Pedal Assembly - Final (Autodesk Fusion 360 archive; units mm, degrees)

design "Pedal Assembly" references "Large Bearing", "Pedal Cap", "Cheese Head Screw ISO 7048 - M3 x 20 - H Steel 4.6 Plain", "O-ring", "Hexagon Thin Nut ISO 4035 - M3 Steel 6 Plain", "Spindle", "Hex Nut", "Small Bearing", "Pedal"
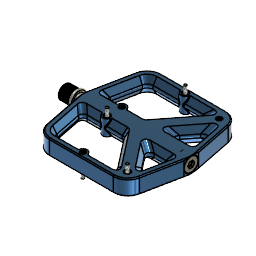
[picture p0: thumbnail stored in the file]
part number: 2025-12-16-16-23-51-010
component_insert "Component Insert1"
component_insert "Component Insert2"
component_insert "Component Insert3"
component_insert "Component Insert4"
component_insert "Component Insert5"
component_insert "Component Insert6"
component_insert "Component Insert7"
step "GeometricRelationship1" Offset 0 Offset 0
step "GeometricRelationship2" Offset 0 Offset 0
step "GeometricRelationship3" Offset 0 Offset 0
step "GeometricRelationship4" Offset 0
joint "Assemble1" alignAngle 0 alignOffsetX 0 alignOffsetY 0 alignOffsetZ 0
joint "Assemble2" alignAngle 0 alignOffsetX 0 alignOffsetY 0 alignOffsetZ 0
step "Screw1"
joint "Assemble3" alignAngle 0 alignOffsetX 0 alignOffsetY 0 alignOffsetZ 0
step "Screw2"
joint "Assemble4" alignAngle 0 alignOffsetX 20.135 alignOffsetY -60 alignOffsetZ 0
joint "Assemble5" alignAngle 0 alignOffsetX 0 alignOffsetY 0 alignOffsetZ -5
step "Screw3"
joint "Assemble6" alignAngle 0 alignOffsetX -40.152 alignOffsetY -99.505 alignOffsetZ 0
joint "Assemble7" alignAngle 0 alignOffsetX 0 alignOffsetY 0 alignOffsetZ -5
step "Screw4"
joint "Assemble8" alignAngle 0 alignOffsetX 0 alignOffsetY 0 alignOffsetZ 0
step "Screw5"
joint "Assemble9" alignAngle 0 alignOffsetX 20.135 alignOffsetY -60 alignOffsetZ 0
joint "Assemble10" alignAngle 0 alignOffsetX 0 alignOffsetY 0 alignOffsetZ 5
step "Screw6"
joint "Assemble11" alignAngle 0 alignOffsetX -40.152 alignOffsetY -99.505 alignOffsetZ 0
joint "Assemble12" alignAngle 0 alignOffsetX 0 alignOffsetY 0 alignOffsetZ 5
step "Nut7"
joint "Assemble13" alignAngle 0 alignOffsetX 40.152 alignOffsetY -99.505 alignOffsetZ 0
joint "Assemble14" alignAngle 0 alignOffsetX 0 alignOffsetY 0 alignOffsetZ -0.432
step "Nut8"
joint "Assemble15" alignAngle 0 alignOffsetX 60.288 alignOffsetY -39.505 alignOffsetZ 0
joint "Assemble16" alignAngle 0 alignOffsetX 0 alignOffsetY 0 alignOffsetZ -0.432
step "Nut9"
joint "Assemble17" alignAngle 0 alignOffsetX 0 alignOffsetY 0 alignOffsetZ 0
joint "Assemble18" alignAngle 0 alignOffsetX 0 alignOffsetY 0 alignOffsetZ -0.432
step "Nut10"
joint "Assemble19" alignAngle 0 alignOffsetX 40.152 alignOffsetY -99.505 alignOffsetZ 0
joint "Assemble20" alignAngle 0 alignOffsetX 0 alignOffsetY 0 alignOffsetZ -0.432
step "Nut11"
joint "Assemble21" alignAngle 0 alignOffsetX 60.288 alignOffsetY -39.505 alignOffsetZ 0
joint "Assemble22" alignAngle 0 alignOffsetX 0 alignOffsetY 0 alignOffsetZ -0.432
step "Nut12"
joint "Assemble23" alignAngle 0 alignOffsetX 0 alignOffsetY 0 alignOffsetZ 0
joint "Assemble24" alignAngle 0 alignOffsetX 0 alignOffsetY 0 alignOffsetZ -0.432

design "Pedal"
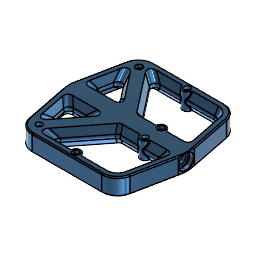
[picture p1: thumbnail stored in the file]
part number: 2025-12-16-15-12-29-748
sketch "Sketch1" plane through (0, 0, 0) normal (0, 0, 1) x axis (1, 0, 0)
  line L1 (55, -7.5) -> (-55, -7.5)
  line L2 (55, 7.5) -> (55, -7.5)
  line L3 (-55, 7.5) -> (55, 7.5)
  line L4 (-55, -7.5) -> (-55, 7.5)
  line L5 (55, 7.5) -> (-55, -7.5)
  line L6 (-55, 7.5) -> (55, -7.5)
  line L7 (55, 0) -> (-55, 0)
  line L8 (45, 57.5) -> (-45, 57.5)
  line L9 (-45, 57.5) -> (-55, 7.5)
  line L10 (55, 7.5) -> (45, 57.5)
  line L11 (-45, -57.5) -> (-55, -7.5)
  line L12 (45, -57.5) -> (-45, -57.5)
  line L13 (55, -7.5) -> (45, -57.5)
  point P6 (0, 0)
  point P1 (0, 0)
  point P7 (-55, 0)
  point P8 (55, 0)
  point P4 (55, 7.5)
  point P14 (55, -7.5)
  point P5 (-55, 7.5)
  point P11 (-55, -7.5)
  point P9 (-45, 57.5)
  point P12 (-45, -57.5)
  point P10 (45, 57.5)
  point P13 (45, -57.5)
  point P3 (55, -7.5)
  horizontal L1
  perpendicular L1 L2
  parallel L1 L3
  parallel L2 L4
  coincident L5 P6
  coincident L6 P6
  coincident P1 P6
  midpoint L4 P7
  midpoint L2 P8
  horizontal L8
  equal L9 L10
  symmetric P4 L7 P14
  symmetric P5 L7 P11
  symmetric L7 P9 P12
  symmetric L7 P10 P13
  dimension "d1" distance P4 P5 = 110
  dimension "d2" distance P3 P4 = 15
  dimension "d3" distance L7 L8 = 57.5
  dimension "d4" distance P9 P10 = 90
extrude "Extrude1" new body sketch "Sketch1" profile of L2 L4 L8 L9 L10 L11 L12 L13 distance 16
fillet "Fillet1" radius 15
sketch "Sketch2" plane through (0, 0, 8) normal (0, 0, 1) x axis (-1, 0, 0)
  line L1 (-55, 7.5) -> (-47.4117, 45.4417)
  line L2 (-55, -7.5) -> (-55, 7.5)
  line L3 (-47.4117, -45.4417) -> (-55, -7.5)
  line L4 (32.7029, -57.5) -> (-32.7029, -57.5)
  line L5 (55, -7.5) -> (47.4117, -45.4417)
  line L6 (55, 7.5) -> (55, -7.5)
  line L7 (47.4117, 45.4417) -> (55, 7.5)
  line L8 (-32.7029, 57.5) -> (32.7029, 57.5)
  line L9 (-55, -7.5) -> (55, -7.5)
  line L10 (-55, 7.5) -> (55, 7.5)
  line L11 (42.2128, -54.1001) -> (0, 0)
  line L12 (42.2128, 54.1001) -> (0, 0)
  line L13 (45.5479, 50.2465) -> (6.342, 0)
  line L14 (45.5479, -50.2465) -> (6.342, 0)
  line L15 (37.8212, 56.5998) -> (-6.342, 0)
  line L16 (37.8212, -56.5998) -> (-6.342, 0)
  line L17 (50, -7.0049) -> (42.5087, -44.4612)
  line L18 (50, 7.0049) -> (50, -7.0049)
  line L19 (42.5087, 44.4612) -> (50, 7.0049)
  line L20 (-32.7029, 52.5) -> (32.7029, 52.5)
  line L21 (-50, 7.0049) -> (-42.5087, 44.4612)
  line L22 (-50, -7.0049) -> (-50, 7.0049)
  line L23 (-42.5087, -44.4612) -> (-50, -7.0049)
  line L24 (32.7029, -52.5) -> (-32.7029, -52.5)
  arc A1 centre (-32.7029, 42.5) radius 15 clockwise from (-47.4117, 45.4417) to (-32.7029, 57.5)
  arc A2 centre (-32.7029, -42.5) radius 15 clockwise from (-32.7029, -57.5) to (-47.4117, -45.4417)
  arc A3 centre (32.7029, -42.5) radius 15 clockwise from (47.4117, -45.4417) to (32.7029, -57.5)
  arc A4 centre (32.7029, 42.5) radius 15 clockwise from (32.7029, 57.5) to (47.4117, 45.4417)
  arc A5 centre (32.7029, -42.5) radius 10 clockwise from (42.5087, -44.4612) to (32.7029, -52.5)
  arc A6 centre (32.7029, 42.5) radius 10 clockwise from (32.7029, 52.5) to (42.5087, 44.4612)
  arc A7 centre (-32.7029, 42.5) radius 10 clockwise from (-42.5087, 44.4612) to (-32.7029, 52.5)
  arc A8 centre (-32.7029, -42.5) radius 10 clockwise from (-32.7029, -52.5) to (-42.5087, -44.4612)
  point P13 (55, -7.5)
  point P18 (55, -7.5)
  point P6 (-55, -7.5)
  point P19 (-55, -7.5)
  point P14 (55, 7.5)
  point P20 (55, 7.5)
  point P5 (-55, 7.5)
  point P21 (-55, 7.5)
  point P1 (0, 0)
  point P22 (0, 0)
  point P23 (42.2128, -54.1001)
  point P24 (0, 0)
  point P25 (42.2128, 54.1001)
  point P31 (37.8212, -56.5998)
  point P28 (45.5479, -50.2465)
  point P27 (45.5479, 50.2465)
  point P30 (37.8212, 56.5998)
  coincident P13 P18
  coincident P6 P19
  coincident P14 P20
  coincident P5 P21
  coincident P1 P22
  midpoint A3 P23
  coincident P1 P24
  midpoint A4 P25
  coincident A3 P31
  coincident A3 P28
  coincident A4 P27
  coincident A4 P30
  dimension "d9" = 5
  dimension "d10" = -5 (= "-d9")
  dimension "d11" = -5
extrude "Extrude2" cut sketch "Sketch2" profile of L9 L10 L13 L14 L15 L16 A6 A5 L17 L19 L20 A7 L21 L23 A8 L24 against normal blind 8 taper -30
fillet "Fillet2" radius 5
mirror "Mirror1" mirrorStitchTolerance 0.1
fillet "Fillet3" ChordLen 3.5
sketch "Sketch3" plane through (0, 0, 0) normal (0, 0, 1) x axis (1, 0, 0)
  line L1 (55, -7.5) -> (55, 7.5)
  line L2 (55, 7.5) -> (55, -7.5)
  line L3 (-55, 7.5) -> (-55, -7.5)
  line L4 (-55, 0) -> (55, 0)
  line L5 (51, 7) -> (55, 7)
  line L6 (51, 4.5) -> (51, 7)
  line L7 (-42.5, 4.5) -> (51, 4.5)
  line L8 (-42.5, 5) -> (-42.5, 4.5)
  line L9 (-45, 5) -> (-42.5, 5)
  line L10 (-45, 7) -> (-45, 5)
  line L11 (-55, 7) -> (-45, 7)
  point P6 (55, 0)
  point P7 (-55, 0)
  point P8 (55, 7)
  point P15 (-55, 7)
  point P9 (51, 7)
  point P10 (51, 4.5)
  point P11 (-42.5, 4.5)
  point P12 (-42.5, 5)
  midpoint L2 P6
  midpoint L3 P7
  coincident L1 P8
  perpendicular L1 L5
  perpendicular L5 L6
  perpendicular L6 L7
  perpendicular L7 L8
  perpendicular L3 L9
  perpendicular L9 L10
  coincident L3 P15
  perpendicular L3 L11
  dimension "d20" = 14
  dimension "d21" distance P8 P9 = 4
  dimension "d22" = 9
  dimension "d23" distance P10 P11 = 93.5
  dimension "d24" = 10
  dimension "d25" distance P12 L10 = 2.5
  dimension "d26" = 14
revolve "Revolve1" sketch "Sketch3" AlongAngle 360
sketch "Screw Loc" plane through (0, 0, 8) normal (0, 0, 1) x axis (-1, 0, 0)
  line L1 (44.0595, -36.7075) -> (48.8651, -12.6793)
  line L2 (17.6511, -14.4939) -> (36.3996, -38.522)
  line L3 (44.6191, -7.5) -> (21.065, -7.5)
  line L4 (-48.8651, -12.6793) -> (-42.5087, -44.4612)
  line L5 (-2.6036, -7.5) -> (-44.6191, -7.5)
  line L6 (29.1652, -45.5061) -> (0.8103, -9.1664)
  line L7 (-32.7029, -52.5) -> (25.7513, -52.5)
  line L8 (48.8651, 12.6793) -> (44.0595, 36.7075)
  line L9 (21.065, 7.5) -> (44.6191, 7.5)
  line L10 (36.3996, 38.522) -> (17.6511, 14.4939)
  line L11 (0.8103, 9.1664) -> (29.1652, 45.5061)
  line L12 (-44.6191, 7.5) -> (-2.6036, 7.5)
  line L13 (-42.5087, 44.4612) -> (-48.8651, 12.6793)
  line L14 (25.7513, 52.5) -> (-32.7029, 52.5)
  line L15 (-55, 7.5) -> (-47.4117, 45.4417)
  line L16 (-55, -7.5) -> (-55, 7.5)
  line L17 (-47.4117, -45.4417) -> (-55, -7.5)
  line L18 (32.7029, -57.5) -> (-32.7029, -57.5)
  line L19 (55, -7.5) -> (47.4117, -45.4417)
  line L20 (55, 7.5) -> (55, -7.5)
  line L21 (47.4117, 45.4417) -> (55, 7.5)
  line L22 (-32.7029, 57.5) -> (32.7029, 57.5)
  line L23 (42.2128, -54.1001) -> (0, 0)
  line L24 (55, 0) -> (0, 0)
  closed curve K1 centre (39.0153, -32.4891)
  closed curve K2 centre (24.022, -13.2735)
  closed curve K3 centre (42.8584, -13.2735)
  closed curve K4 centre (-42.8584, -13.2735)
  closed curve K5 centre (-3.3081, -13.2735)
  closed curve K6 centre (22.7943, -46.7265)
  arc A1 centre (-32.7029, -42.5) radius 10 clockwise from (-32.7029, -52.5) to (-42.5087, -44.4612)
  closed curve K7 centre (42.8584, 13.2735)
  closed curve K8 centre (24.022, 13.2735)
  closed curve K9 centre (39.0153, 32.4891)
  closed curve K10 centre (22.7943, 46.7265)
  closed curve K11 centre (-3.3081, 13.2735)
  closed curve K12 centre (-42.8584, 13.2735)
  arc A2 centre (-32.7029, 42.5) radius 10 clockwise from (-42.5087, 44.4612) to (-32.7029, 52.5)
  arc A3 centre (-32.7029, 42.5) radius 15 clockwise from (-47.4117, 45.4417) to (-32.7029, 57.5)
  arc A4 centre (-32.7029, -42.5) radius 15 clockwise from (-32.7029, -57.5) to (-47.4117, -45.4417)
  arc A5 centre (32.7029, -42.5) radius 15 clockwise from (47.4117, -45.4417) to (32.7029, -57.5)
  arc A6 centre (32.7029, 42.5) radius 15 clockwise from (32.7029, 57.5) to (47.4117, 45.4417)
  circle C1 centre (-3.4758, -52.5) radius 4.5
  circle C2 centre (36.6763, -47.0045) radius 4.5
  circle C3 centre (-23.6113, -7.5) radius 4.5
  circle C4 centre (-23.6113, -7.5) radius 2.75
  circle C5 centre (-3.4758, -52.5) radius 2.75
  circle C6 centre (36.6763, -47.0045) radius 2.75
  circle C7 centre (36.6763, 47.0045) radius 4.5
  circle C8 centre (36.6763, 47.0045) radius 2.75
  circle C9 centre (-3.4758, 52.5) radius 4.5
  circle C10 centre (-3.4758, 52.5) radius 2.75
  circle C11 centre (-23.6113, 7.5) radius 4.5
  circle C12 centre (-23.6113, 7.5) radius 2.75
  point P58 (-3.4758, -52.5)
  point P61 (36.6763, -47.0045)
  point P59 (0, 0)
  point P62 (0, 0)
  point P63 (55, 0)
  point P64 (-23.6113, -7.5)
  point P60 (42.2128, -54.1001)
  midpoint L7 P58
  coincident L23 P61
  coincident P59 P62
  midpoint L20 P63
  coincident L5 P64
  midpoint L5 P64
  equal C1 C3
  concentric C3 C4
  concentric C1 C5
  concentric C2 C6
  equal C5 C6
  equal C4 C5
  symmetric C1 L24 C9
  symmetric C2 L24 C7
  symmetric L24 C3 C11
  symmetric L24 C4 C12
  symmetric L24 C5 C10
  symmetric L24 C6 C8
  dimension "d28" diameter C1 = 9
  dimension "d29" diameter C2 = 9
  dimension "d30" distance P60 P61 = 9
  dimension "d31" diameter C4 = 5.5
extrude "Extrude3" add sketch "Screw Loc" profile of L5 L7 L12 L14 C1 C3 C4 C5 C9 C10 C11 C12 to an object
extrude "Extrude4" cut sketch "Screw Loc" profile of L7 L12 C5 C8 C12 against normal blind 3
extrude "Extrude5" sketch "Screw Loc" profile of L5 L14 C4 C6 C10 blind 3
sketch "Sketch5" plane through (0, 0, 8) normal (0, 0, 1) x axis (-1, 0, 0)
  line L1 (44.0595, -36.7075) -> (48.8651, -12.6793)
  line L2 (17.6511, -14.4939) -> (36.3996, -38.522)
  line L3 (44.6191, -7.5) -> (21.065, -7.5)
  line L4 (-48.8651, -12.6793) -> (-42.5087, -44.4612)
  line L5 (-28.1113, -7.5) -> (-44.6191, -7.5)
  line L6 (-2.6036, -7.5) -> (-19.1113, -7.5)
  line L7 (29.1652, -45.5061) -> (0.8103, -9.1664)
  line L8 (1.0242, -52.5) -> (25.7513, -52.5)
  line L9 (-32.7029, -52.5) -> (-7.9758, -52.5)
  line L10 (48.8651, 12.6793) -> (44.0595, 36.7075)
  line L11 (21.065, 7.5) -> (44.6191, 7.5)
  line L12 (36.3996, 38.522) -> (17.6511, 14.4939)
  line L13 (0.8103, 9.1664) -> (29.1652, 45.5061)
  line L14 (-19.1113, 7.5) -> (-2.6036, 7.5)
  line L15 (-44.6191, 7.5) -> (-28.1113, 7.5)
  line L16 (-42.5087, 44.4612) -> (-48.8651, 12.6793)
  line L17 (-7.9758, 52.5) -> (-32.7029, 52.5)
  line L18 (25.7513, 52.5) -> (1.0242, 52.5)
  line L19 (-55, 7.5) -> (-47.4117, 45.4417)
  line L20 (-55, -7.5) -> (-55, 7.5)
  line L21 (-47.4117, -45.4417) -> (-55, -7.5)
  line L22 (32.7029, -57.5) -> (-32.7029, -57.5)
  line L23 (55, -7.5) -> (47.4117, -45.4417)
  line L24 (55, 7.5) -> (55, -7.5)
  line L25 (47.4117, 45.4417) -> (55, 7.5)
  line L26 (-32.7029, 57.5) -> (32.7029, 57.5)
  line L27 (-0.6008, -54.1599) -> (-3.4758, -55.8198)
  line L28 (-0.6008, -50.8401) -> (-0.6008, -54.1599)
  line L29 (-3.4758, -49.1802) -> (-0.6008, -50.8401)
  line L30 (-6.3508, -50.8401) -> (-3.4758, -49.1802)
  line L31 (-6.3508, -54.1599) -> (-6.3508, -50.8401)
  line L32 (-3.4758, -55.8198) -> (-6.3508, -54.1599)
  line L33 (39.5513, -48.6644) -> (36.6763, -50.3243)
  line L34 (39.5513, -45.3447) -> (39.5513, -48.6644)
  line L35 (36.6763, -43.6848) -> (39.5513, -45.3447)
  line L36 (33.8013, -45.3447) -> (36.6763, -43.6848)
  line L37 (33.8013, -48.6644) -> (33.8013, -45.3447)
  line L38 (36.6763, -50.3243) -> (33.8013, -48.6644)
  line L39 (-23.6113, -10.8198) -> (-26.4863, -9.1599)
  line L40 (-20.7363, -9.1599) -> (-23.6113, -10.8198)
  line L41 (-20.7363, -5.8401) -> (-20.7363, -9.1599)
  line L42 (-23.6113, -4.1802) -> (-20.7363, -5.8401)
  line L43 (-26.4863, -5.8401) -> (-23.6113, -4.1802)
  line L44 (-26.4863, -9.1599) -> (-26.4863, -5.8401)
  line L45 (-20.7363, 5.8401) -> (-23.6113, 4.1802)
  line L46 (-20.7363, 9.1599) -> (-20.7363, 5.8401)
  line L47 (-23.6113, 10.8198) -> (-20.7363, 9.1599)
  line L48 (-26.4863, 9.1599) -> (-23.6113, 10.8198)
  line L49 (-26.4863, 5.8401) -> (-26.4863, 9.1599)
  line L50 (-23.6113, 4.1802) -> (-26.4863, 5.8401)
  line L51 (-0.6008, 50.8401) -> (-3.4758, 49.1802)
  line L52 (-0.6008, 54.1599) -> (-0.6008, 50.8401)
  line L53 (-3.4758, 55.8198) -> (-0.6008, 54.1599)
  line L54 (-6.3508, 54.1599) -> (-3.4758, 55.8198)
  line L55 (-6.3508, 50.8401) -> (-6.3508, 54.1599)
  line L56 (-3.4758, 49.1802) -> (-6.3508, 50.8401)
  line L57 (39.5513, 45.3447) -> (36.6763, 43.6848)
  line L58 (39.5513, 48.6644) -> (39.5513, 45.3447)
  line L59 (36.6763, 50.3243) -> (39.5513, 48.6644)
  line L60 (33.8013, 48.6644) -> (36.6763, 50.3243)
  line L61 (33.8013, 45.3447) -> (33.8013, 48.6644)
  line L62 (36.6763, 43.6848) -> (33.8013, 45.3447)
  circle C1 centre (36.6763, 47.0045) radius 2.75
  circle C2 centre (-23.6113, 7.5) radius 2.75
  circle C3 centre (-3.4758, -52.5) radius 2.75
  closed curve K1 centre (39.0153, -32.4891)
  closed curve K2 centre (24.022, -13.2735)
  closed curve K3 centre (42.8584, -13.2735)
  closed curve K4 centre (-42.8584, -13.2735)
  arc A1 centre (-23.6113, -7.5) radius 4.5 clockwise from (-19.1113, -7.5) to (-28.1113, -7.5)
  closed curve K5 centre (-3.3081, -13.2735)
  closed curve K6 centre (22.7943, -46.7265)
  arc A2 centre (-3.4758, -52.5) radius 4.5 clockwise from (-7.9758, -52.5) to (1.0242, -52.5)
  arc A3 centre (-32.7029, -42.5) radius 10 clockwise from (-32.7029, -52.5) to (-42.5087, -44.4612)
  closed curve K7 centre (42.8584, 13.2735)
  closed curve K8 centre (24.022, 13.2735)
  closed curve K9 centre (39.0153, 32.4891)
  closed curve K10 centre (22.7943, 46.7265)
  closed curve K11 centre (-3.3081, 13.2735)
  arc A4 centre (-23.6113, 7.5) radius 4.5 clockwise from (-28.1113, 7.5) to (-19.1113, 7.5)
  closed curve K12 centre (-42.8584, 13.2735)
  arc A5 centre (-32.7029, 42.5) radius 10 clockwise from (-42.5087, 44.4612) to (-32.7029, 52.5)
  arc A6 centre (-3.4758, 52.5) radius 4.5 clockwise from (1.0242, 52.5) to (-7.9758, 52.5)
  arc A7 centre (-32.7029, 42.5) radius 15 clockwise from (-47.4117, 45.4417) to (-32.7029, 57.5)
  arc A8 centre (-32.7029, -42.5) radius 15 clockwise from (-32.7029, -57.5) to (-47.4117, -45.4417)
  arc A9 centre (32.7029, -42.5) radius 15 clockwise from (47.4117, -45.4417) to (32.7029, -57.5)
  arc A10 centre (32.7029, 42.5) radius 15 clockwise from (32.7029, 57.5) to (47.4117, 45.4417)
  point P72 (-3.4758, -52.5)
  point P83 (-3.4758, -52.5)
  point P71 (36.6763, -47.0045)
  point P90 (36.6763, -47.0045)
  point P20 (-23.6113, -7.5)
  point P97 (-23.6113, -7.5)
  point P3 (-23.6113, 7.5)
  point P104 (-23.6113, 7.5)
  point P75 (-3.4758, 52.5)
  point P111 (-3.4758, 52.5)
  point P76 (36.6763, 47.0045)
  point P118 (36.6763, 47.0045)
  coincident P72 P83
  vertical L28
  coincident P71 P90
  coincident P20 P97
  coincident P3 P104
  coincident P75 P111
  coincident P76 P118
  vertical L61
  vertical L52
  vertical L46
  vertical L44
  vertical L37
  equal L31 L37
  equal L31 L44
  equal L44 L49
  equal L49 L55
  equal L55 L61
  dimension "d39" distance L28 L31 = 5.75
extrude "Extrude6" cut sketch "Sketch5" profile of L33 L34 L35 L36 L37 L38 L39 L40 L41 L42 L43 L44 L51 L52 L53 L54 L55 L56 against normal blind 3
extrude "Extrude7" sketch "Sketch5" profile of C1 C2 C3 L27 L28 L29 L30 L31 L32 L45 L46 L47 L48 L49 L50 L57 L58 L59 L60 L61 L62 blind 3
hole "Hole1" HoleDiameter 3 TipAngle 180
fillet "Fillet4" ChordLen 1
chamfer "Chamfer1" distance 1
chamfer "Chamfer2" distance 0.25
thread "Thread1" ThreadOffset 0 ThreadLength 10
chamfer "Chamfer3" distance 0.25
chamfer "Chamfer4" distance 1

design "Pedal Cap"
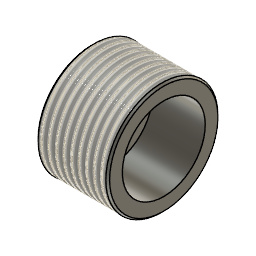
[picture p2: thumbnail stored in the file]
part number: 2025-12-16-11-19-28-387
sketch "Sketch1" plane through (0, 0, 0) normal (0, 0, 1) x axis (1, 0, 0)
  line L1 (7, 0) -> (0, 0)
  line L2 (0, 5.5) -> (0, 0)
  line L3 (7, 5.5) -> (0, 5.5)
  line L4 (7, 7.5) -> (7, 5.5)
  line L5 (-2.5, 7.5) -> (7, 7.5)
  line L6 (-2.5, 0) -> (-2.5, 7.5)
  line L7 (0, 0) -> (-2.5, 0)
  point P1 (0, 0)
  point P2 (0, 0)
  point P4 (0, 0)
  point P10 (0, 0)
  point P3 (7, 0)
  point P9 (-2.5, 0)
  point P5 (0, 5.5)
  point P6 (7, 5.5)
  coincident P1 P2
  horizontal L1
  coincident P1 P4
  perpendicular L1 L2
  perpendicular L2 L3
  perpendicular L3 L4
  perpendicular L4 L5
  perpendicular L1 L6
  coincident P1 P10
  perpendicular L2 L7
  coincident P3 L4
  dimension "d1" distance P2 P3 = 7
  dimension "d2" = 11
  dimension "d3" = 15
  dimension "d4" distance P9 P10 = 2.5
  dimension "d5" distance P5 P6 = 7
revolve "Revolve1" sketch "Sketch1" AlongAngle 360
sketch "Sketch2" plane through (-2.5, 0, 0) normal (-1, 0, 0) x axis (0, -1, 0)
  line L1 (-3.4641, 0) -> (-1.7321, 3)
  line L2 (-1.7321, -3) -> (-3.4641, 0)
  line L3 (1.7321, -3) -> (-1.7321, -3)
  line L4 (3.4641, 0) -> (1.7321, -3)
  line L5 (1.7321, 3) -> (3.4641, 0)
  line L6 (-1.7321, 3) -> (1.7321, 3)
  circle C1 centre (0, 0) radius 7.5
  point P1 (0, 0)
  point P9 (0, 0)
  coincident P1 P9
  horizontal L6
  dimension "d7" distance L3 L6 = 6
extrude "Extrude1" cut sketch "Sketch2" profile of L1 L2 L3 L4 L5 L6 against normal blind 2
thread "Thread1" ThreadOffset 0 ThreadLength 10
chamfer "Chamfer1" distance 0.25

design "Hexagon Thin Nut ISO 4035 - M3 Steel 6 Plain"
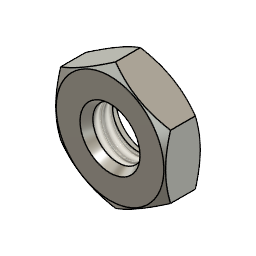
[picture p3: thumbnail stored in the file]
description: Hexagon Thin Nut ISO 4035 - M3
part number: ISO 4035 - M3 Steel 6 Plain
parameter "adsk_nheig" = 1.8
parameter "adsk_maxdia" = 6.3525
parameter "adsk_nomdia" = 3
parameter "adsk_waflat" = 5.5
parameter "adsk_chamang1" = 30
parameter "adsk_chamang2" = 30
parameter "adsk_beardia" = 5.39
sketch "Sketch1" plane through (0, 0, 0) normal (0, 1, 0) x axis (1, 0, 0)
  line L1 (0, -1.8) -> (0, 0)
  line L2 (-2.695, 0) -> (-1.5, 0)
  line L3 (-3.1763, -0.2778) -> (-2.695, 0)
  line L4 (-3.1763, -1.5222) -> (-3.1763, -0.2778)
  line L5 (-2.695, -1.8) -> (-3.1763, -1.5222)
  line L6 (-1.5, -1.8) -> (-2.695, -1.8)
  line L7 (-1.5, 0) -> (-1.5, -1.8)
  point P3 (0, -1.8)
  point P1 (0, 0)
  point P2 (0, 0)
  point P10 (0, 0)
  point P5 (-2.695, 0)
  point P8 (-2.695, -1.8)
  vertical L1
  coincident L1 P3
  coincident P1 L1
  horizontal L2
  coincident P1 L2
  coincident P2 P10
  coincident P3 L6
  vertical P5 P8
  dimension "d121" = 3 (= "adsk_nomdia")
  dimension "d122" angle L2 L3 = 30 (= "adsk_chamang1")
  dimension "d123" angle L5 L6 = 30 (= "adsk_chamang2")
  dimension "d128" = 6.3525 (= "adsk_maxdia")
  dimension "d172" = 5.39 (= "adsk_beardia")
  dimension "d179" distance L2 L6 = 1.8 (= "adsk_nheig")
revolve "Revolve1" sketch "Sketch1" AlongAngle 360
sketch "Sketch8" plane through (0, 0, 1.8) normal (0, 0, 1) x axis (1, 0, 0)
  line L1 (-2.75, 1.5894) -> (-2.75, -1.5894)
  circle C1 centre (0, 0) radius 1.5
  circle C2 centre (0, 0) radius 3.1763
  point P3 (-2.75, 1.5894)
  point P2 (-2.75, -1.5894)
  point P1 (0, 0)
  coincident P3 C2
  coincident P2 C2
  vertical L1
  dimension "d114" distance P1 L1 = 2.75 (= "adsk_waflat / 2")
extrude "Extrude5" cut sketch "Sketch8" profile of L1 C2 no distance stored
circular_pattern "C-Pattern2" TotalAngle 360
thread "Thread3" ThreadOffset 0 ThreadLength 10
sketch "Sketch12" plane through (0, 0, 0) normal (0, 1, 0) x axis (1, 0, 0)
  line L1 (0, 0) -> (-1.5, 0)
  line L2 (-1.5, 0) -> (-0.9804, -0.9)
  line L3 (0, -1.8) -> (-1.5, -1.8)
  line L4 (-1.5, -1.8) -> (-0.9804, -0.9)
  line L5 (0, -1.8) -> (0, 0)
  point P4 (-0.9804, -0.9)
  point P7 (-0.9804, -0.9)
  point P2 (-1.5, 0)
  point P5 (-1.5, -1.8)
  point P6 (0, -1.8)
  point P9 (0, -1.8)
  point P1 (0, 0)
  point P3 (0, 0)
  horizontal L1
  coincident P4 P7
  vertical P2 P5
  coincident P6 P9
  coincident P1 P3
  perpendicular L3 L5
  dimension "d169" angle L3 L4 = 60
  dimension "d177" distance P2 L5 = 1.5 (= "adsk_nomdia * 0.5")
  dimension "d178" angle L1 L2 = 60
revolve "Revolve3" sketch "Sketch12" AlongAngle 360
joint_origin "JointOrigin9" OffsetX 0 OffsetY 0 OffsetZ 0 AngleZ 0
joint_origin "JointOrigin10" OffsetX 0 OffsetY 0 OffsetZ 1.8 (= "adsk_nheig") AngleZ 0

design "O-ring"
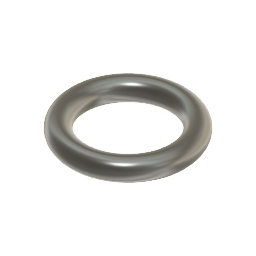
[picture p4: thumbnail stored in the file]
part number: 2025-12-16-11-03-49-491
sketch "Sketch1" plane through (0, 0, 0) normal (0, 1, 0) x axis (1, 0, 0)
  line L1 (0, -31.5008) -> (0, 0)
  circle C1 centre (6, 0) radius 1.25
  point P1 (0, 0)
  point P2 (0, 0)
  point P4 (6, 0)
  coincident P1 P2
  vertical L1
  horizontal P1 P4
  dimension "d1" diameter C1 = 2.5
  dimension "d2" = 12
revolve "Revolve1" sketch "Sketch1" AlongAngle 360

design "Large Bearing"
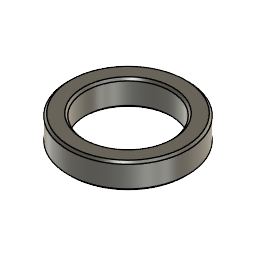
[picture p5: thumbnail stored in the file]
part number: 2025-12-16-10-52-09-464
sketch "Sketch1" plane through (0, 0, 0) normal (0, 0, 1) x axis (1, 0, 0)
  circle C1 centre (0, 0) radius 5
  circle C2 centre (0, 0) radius 7
  point P1 (0, 0)
  point P2 (0, 0)
  coincident P1 P2
  concentric C1 C2
  dimension "d1" diameter C2 = 14
  dimension "d2" diameter C1 = 10
extrude "Extrude1" new body sketch "Sketch1" along normal blind 3
chamfer "Chamfer1" distance 0.25

design "Small Bearing"
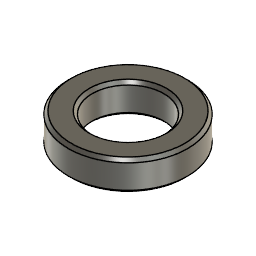
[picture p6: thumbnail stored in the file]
part number: 2025-12-16-11-00-29-093
sketch "Sketch1" plane through (0, 0, 0) normal (0, 0, 1) x axis (1, 0, 0)
  circle C1 centre (0, 0) radius 5
  circle C2 centre (0, 0) radius 3
  point P1 (0, 0)
  point P2 (0, 0)
  point P3 (0, 0)
  coincident P1 P2
  coincident P1 P3
  dimension "d1" diameter C1 = 10
  dimension "d2" diameter C2 = 6
extrude "Extrude1" new body sketch "Sketch1" along normal blind 2.5
chamfer "Chamfer1" distance 0.25

design "Hex Nut"
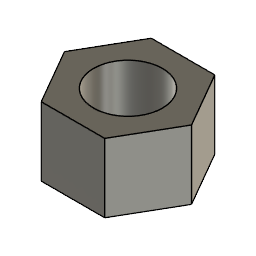
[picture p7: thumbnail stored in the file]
part number: 2025-12-16-11-09-20-013
sketch "Sketch1" plane through (0, 0, 0) normal (0, 0, 1) x axis (1, 0, 0)
  line L1 (-4.6188, 0) -> (-2.3094, 4)
  line L2 (-2.3094, -4) -> (-4.6188, 0)
  line L3 (2.3094, -4) -> (-2.3094, -4)
  line L4 (4.6188, 0) -> (2.3094, -4)
  line L5 (2.3094, 4) -> (4.6188, 0)
  line L6 (-2.3094, 4) -> (2.3094, 4)
  circle C1 centre (0, 0) radius 2.5
  point P1 (0, 0)
  point P2 (0, 0)
  point P9 (0, 0)
  coincident P1 P2
  coincident P1 P9
  horizontal L6
  dimension "d1" diameter C1 = 5
  dimension "d2" distance L3 L6 = 8
extrude "Extrude1" new body sketch "Sketch1" along normal blind 5

design "Cheese Head Screw ISO 7048 - M3 x 20 - H Steel 4.6 Plain"
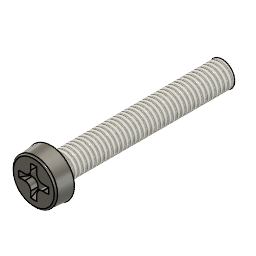
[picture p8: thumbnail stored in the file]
description: Cheese Head Screw ISO 7048 - M3 x 20 - H
part number: ISO 7048 - H - M3 x 20 Steel 4.6 Plain
parameter "adsk_nomdia" = 3
parameter "adsk_nomlen" = 20
parameter "adsk_headdia" = 5.5
parameter "adsk_phildia" = 3.5
parameter "adsk_midfillet" = 0.1
parameter "adsk_phildepth" = 0.86
parameter "adsk_shnklen" = 1
parameter "adsk_thrang" = 15
parameter "adsk_headang" = 5
parameter "adsk_philwidth" = 0.7
parameter "adsk_headh" = 2
parameter "adsk_pitch1" = 0.5
parameter "adsk_shnkdia" = 2.65 (= "adsk_nomdia - 0.7 * adsk_pitch1")
parameter "adsk_headtoprad" = 0.2 (= "adsk_headh * 0.1")
sketch "Sketch1" plane through (0, 0, 0) normal (0, 1, 0) x axis (1, 0, 0)
  line L1 (0, 20) -> (0, -2)
  line L2 (-2.575, -2) -> (-2.75, 0)
  line L3 (-1.325, 0) -> (-2.75, 0)
  line L4 (-1.5, 20) -> (0, 20)
  line L5 (-1.5, 1) -> (-1.5, 20)
  line L6 (-1.325, 0.3469) -> (-1.5, 1)
  line L7 (-1.325, 0) -> (-1.325, 0.3469)
  line L8 (-2.575, -2) -> (0, -2)
  point P1 (0, 0)
  point P5 (-1.325, 0)
  point P9 (-1.325, 0)
  point P4 (-2.75, 0)
  point P7 (-1.5, 1)
  vertical L1
  coincident P1 L1
  coincident P1 L3
  perpendicular L1 L4
  coincident P5 P9
  perpendicular L1 L8
  dimension "d13" angle L1 L2 = 5 (= "adsk_headang")
  dimension "d14" = 5.5 (= "adsk_headdia")
  dimension "d18" = 3 (= "adsk_nomdia")
  dimension "d56" distance L3 L4 = 20 (= "adsk_nomlen")
  dimension "d65" angle L6 L7 = 15 (= "adsk_thrang")
  dimension "d67" distance P4 L8 = 2 (= "adsk_headh")
  dimension "d71" = 2.65 (= "adsk_shnkdia")
  dimension "d77" distance L3 P7 = 1 (= "adsk_shnklen")
revolve "Revolve1" sketch "Sketch1" AlongAngle 360
fillet "Fillet3" radius 0.2 (= "adsk_headtoprad")
fillet "Fillet2" radius 0.1 (= "adsk_midfillet")
sketch "Sketch2" plane through (0, 0, 2) normal (0, 0, 1) x axis (1, 0, 0)
  line L1 (-1.75, 0.35) -> (-0.35, 0.35)
  line L2 (-1.75, -0.35) -> (-1.75, 0.35)
  line L3 (-0.35, -0.35) -> (-1.75, -0.35)
  line L4 (-0.35, -1.75) -> (-0.35, -0.35)
  line L5 (0.35, -1.75) -> (-0.35, -1.75)
  line L6 (0.35, -0.35) -> (0.35, -1.75)
  line L7 (1.75, -0.35) -> (0.35, -0.35)
  line L8 (1.75, 0.35) -> (1.75, -0.35)
  line L9 (0.35, 0.35) -> (1.75, 0.35)
  line L10 (0.35, 1.75) -> (0.35, 0.35)
  line L11 (-0.35, 1.75) -> (0.35, 1.75)
  line L12 (-0.35, 0.35) -> (-0.35, 1.75)
  point P2 (-0.35, 0.35)
  point P5 (-0.35, -0.35)
  point P6 (-0.35, -0.35)
  point P11 (1.75, -0.35)
  horizontal L1
  perpendicular L1 L2
  vertical P2 P5
  coincident P5 P6
  dimension "d83" distance L1 L3 = 0.7 (= "adsk_philwidth")
  dimension "d84" distance L2 P11 = 3.5 (= "adsk_phildia")
  dimension "d81" C-Pattern1-Angle = 360
extrude "Extrude1" new body sketch "Sketch2" no distance stored
draft "Draft1" Angle1 -30 Angle2 0
fillet "Fillet1" radius 0.7 (= "adsk_philwidth")
combine "Combine1"
thread "Thread3" ThreadOffset 0 ThreadLength 10
joint_origin "JointOrigin1" OffsetX 0 OffsetY 0 OffsetZ 0 AngleZ 0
